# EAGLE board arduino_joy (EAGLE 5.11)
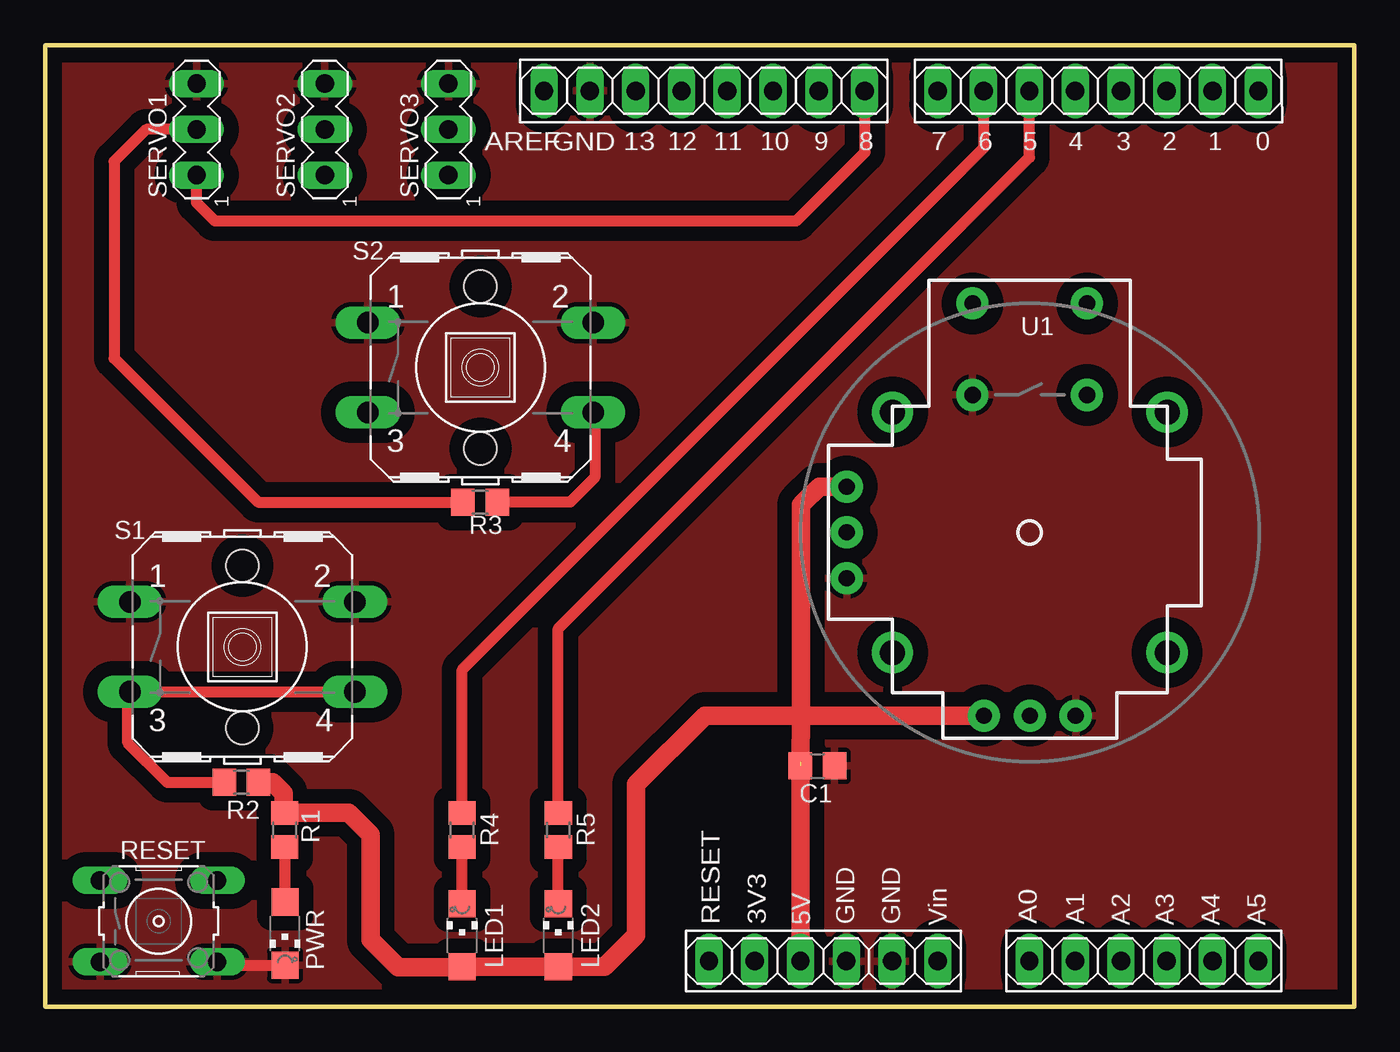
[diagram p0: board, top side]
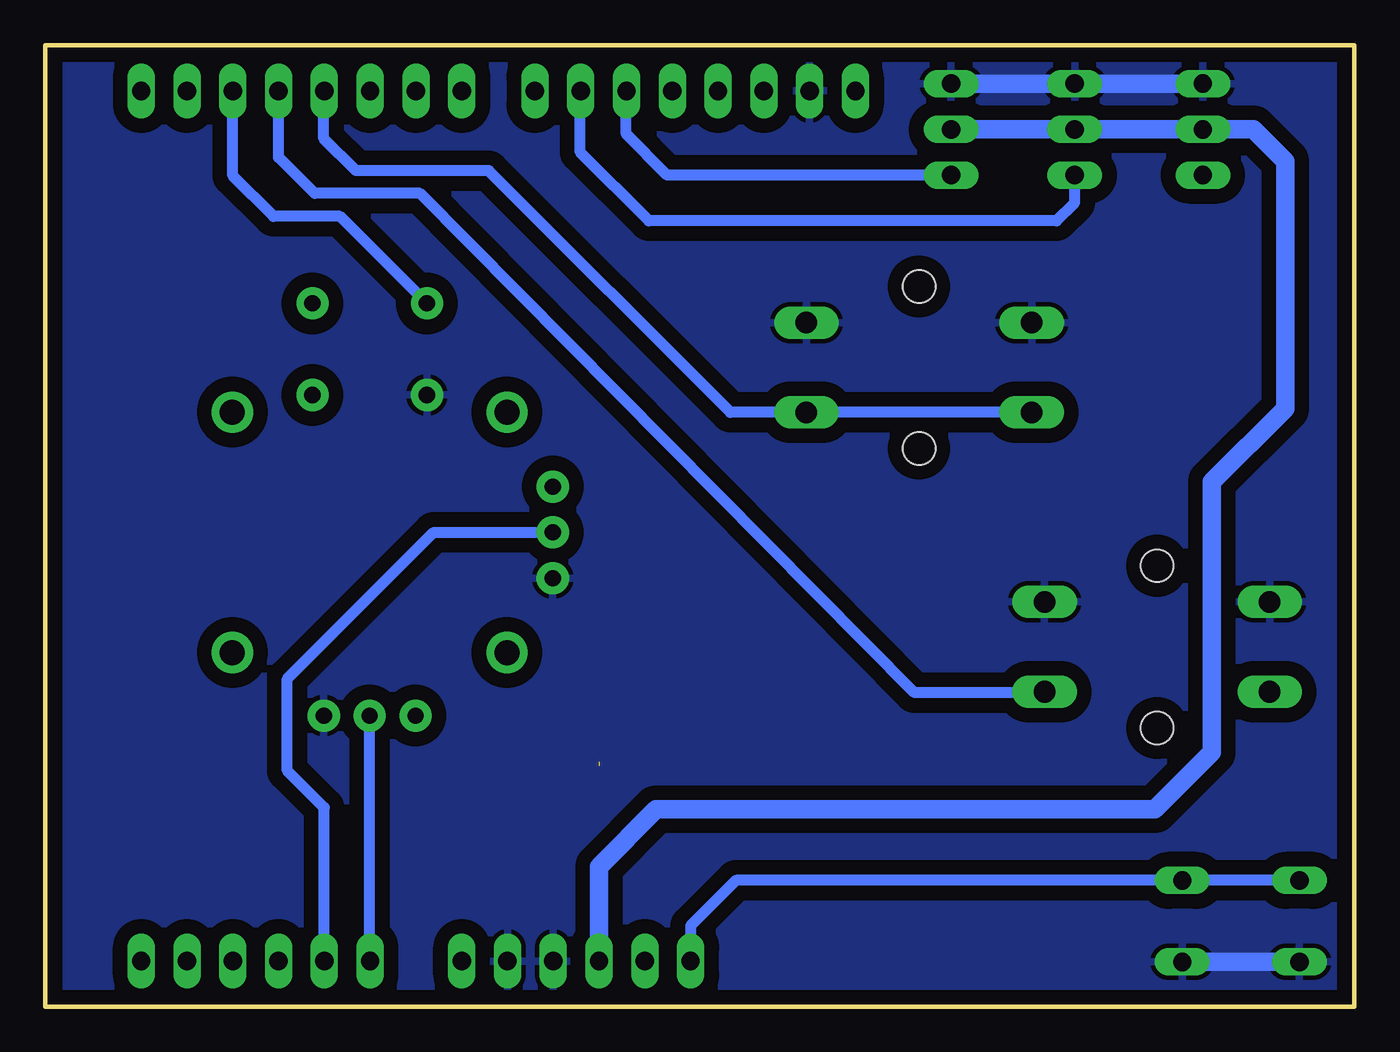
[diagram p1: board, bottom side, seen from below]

Size 72.64 x 53.34 mm. Coordinates in mm from the lower left corner, seen from the top.
Outline: 0,53.34 72.64,53.34 72.64,0 0,0 0,53.34
Copper layers (1*16): Top 0.035mm / dielectric 1.5mm / Bottom 0.035mm
Design rules "default *": minimum track width 16mil, minimum drill 24mil, track to track 8mil, track to pad 8mil, pad to pad 8mil, via to via 8mil, smd to smd 8mil, copper to edge 20mil, drill to drill 8mil, minimum pad ring 10mil, minimum via ring 8mil, stop-mask expansion 4mil, vias tented up to drill 0mil, thermal gap 10mil
Net classes: 0 default: width 0.254 mm, drill 0.305 mm, clearance 0.152 mm; 1 power: width 0.61 mm, drill 0.508 mm, clearance 0.152 mm; 2 gnd: width 0.305 mm, drill 0.508 mm, clearance 0.152 mm; 3 usbvcc: width 0.508 mm, drill 0.508 mm, clearance 0.152 mm; 4 aref: width 0.406 mm

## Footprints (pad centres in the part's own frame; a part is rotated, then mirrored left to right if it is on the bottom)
C0805 = smd 1.3 x 1.5: 1 -0.95,0; 2 0.95,0
1X08 = drill 1.016 long: 1 -8.89,0; 2 -6.35,0; 3 -3.81,0; 4 -1.27,0; 5 1.27,0; 6 3.81,0; 7 6.35,0; 8 8.89,0
1X06 = drill 1.016 long: 1 -6.35,0; 2 -3.81,0; 3 -1.27,0; 4 1.27,0; 5 3.81,0; 6 6.35,0
CHIPLED_1206 = smd 1.5 x 1.5: A 0,-1.75; C 0,1.75
R0805 = smd 1.3 x 1.5: 1 -0.95,0; 2 0.95,0
B3F-10XX = drill 1.016 long: 1 -3.251,2.261; 2 3.251,2.261; 3 -3.251,-2.261; 4 3.251,-2.261
B3F-40XX = drill 1.194 long: 1 -6.248,2.489; 2 6.248,2.489; 3 -6.248,-2.489; 4 6.248,-2.489 | hole 1.803: 0,-4.496; 0,4.496
MA03-1 = drill 1.016 long: 1 -2.54,0; 2 0,0; 3 2.54,0
JOYSTICK = drill 0.9 pad 1.778 round: B1A -3.175,12.7; B1B 3.175,12.7; B2A -3.175,7.62; B2B 3.175,7.62 | drill 0.889 pad 1.778 round: H1 -2.54,-10.16; H2 0,-10.16; H3 2.54,-10.16; V1 -10.16,2.54; V2 -10.16,0; V3 -10.16,-2.54 | drill 1.397 pad 2.286 round: MOUNT1 -7.62,6.668; MOUNT2 -7.62,-6.668; MOUNT3 7.62,-6.668; MOUNT4 7.62,6.668

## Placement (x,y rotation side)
C1  100nF  [C0805]  42.85,13.36 0 top
J1  [1X08]  58.42,50.8 180 top
J2  [1X06]  60.96,2.54 0 top
J3  [1X08]  36.58,50.8 180 top
LED1  [CHIPLED_1206]  23.14,3.96 0 top
LED2  [CHIPLED_1206]  28.47,3.96 0 top
POWER  [1X06]  43.18,2.54 0 top
PWR  [CHIPLED_1206]  13.31,4.06 180 top
R1  1k  [R0805]  13.28,9.8 90 top
R2  10k  [R0805]  10.9,12.45 180 top
R3  10k  [R0805]  24.13,27.99 0 top
R4  [R0805]  23.14,9.8 90 top
R5  [R0805]  28.47,9.8 90 top
RESET  [B3F-10XX]  6.3,4.75 0 top
S1  [B3F-40XX]  10.95,19.96 0 top
S2  [B3F-40XX]  24.16,35.46 0 top
SERVO1  [MA03-1]  8.41,48.67 90 top
SERVO2  [MA03-1]  15.52,48.67 90 top
SERVO3  [MA03-1]  22.38,48.67 90 top
U1  JOYSTICKPTH  [JOYSTICK]  54.64,26.31 0 top

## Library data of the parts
C1 R1-R5 = rcl
J1-J3 POWER = pinhead
LED1 LED2 PWR = led
RESET = switch-omron; MPN: B3F-1000; OC_FARNELL: 176432; OC_NEWARK: 36M3542
S1 S2 = switch-omron; MF: OMRON COMPONENTS USA; MPN: B3F-4000; OC_FARNELL: 176434; OC_NEWARK: 36K3105
SERVO1-SERVO3 = con-lstb; OC_FARNELL: unknown; OC_NEWARK: unknown
U1 = SparkFun

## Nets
+5V [usbvcc]: C1.1 LED1.A LED2.A POWER.3 R1.2 R2.1 R3.1 SERVO1.2 SERVO2.2 SERVO3.2 U1.H1 U1.V1
AREF: J3.8
GND [power]: C1.2 J3.7 POWER.4 POWER.5 PWR.C RESET.3 RESET.4 S1.1 S1.2 S2.1 S2.2 SERVO1.3 SERVO2.3 SERVO3.3 U1.B2A U1.H3 U1.V3
N$1: LED1.C R4.1
N$2: LED2.C R5.1
N$8: PWR.A R1.1
PB0: J3.1 SERVO1.1
PB1: J3.2 SERVO2.1
PB2: J3.3 SERVO3.1
PB3: J3.4
PB4: J3.5
PB5: J3.6
PC0: J2.1 U1.H2
PC1: J2.2 U1.V2
PC2: J2.3
PC3: J2.4
PC4: J2.5
PC5: J2.6
PD0: J1.1
PD1: J1.2
PD2: J1.3 U1.B1A
PD3: J1.4 R2.2 S1.3 S1.4
PD4: J1.5 R3.2 S2.3 S2.4
PD5: J1.6 R5.2
PD6: J1.7 R4.2
PD7: J1.8
RESET: POWER.1 RESET.1 RESET.2
VCC3O: POWER.2
VIN: POWER.6

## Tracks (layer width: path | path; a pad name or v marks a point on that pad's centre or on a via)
+5V  (1 unrouted)
  Top 0.61: 23.11,2.18 LED1.A | R3.1 11.81,27.99 3.84,35.97 3.84,46.89 5.61,48.67 SERVO1.2
  Top 1.016: POWER.3 41.91,13.59 41.94,16.15 | 41.94,16.15 U1.H1 | LED1.A LED2.A 31.04,2.21 32.79,3.96 32.79,12.34 36.6,16.15 41.94,16.15 | 23.11,2.18 19.58,2.18 18.06,3.71 18.06,9.55 16.86,10.75 R1.2 13.23,10.81 13.23,11.84 12.62,12.45 R2.1 | SERVO1.2 8.92,48.67 | U1.V1 42.95,28.85 41.94,27.84 41.94,16.15
  Bottom 1.016: SERVO3.2 SERVO2.2 SERVO1.2 5.61,48.67 3.84,46.89 3.84,33.17 7.9,29.11 7.9,14.12 11.07,10.95 38.74,10.95 41.91,7.77 POWER.3
GND
  Top 0.61: PWR.C 9.73,2.31 RESET.4
  Bottom 1.016: SERVO1.3 SERVO2.3 SERVO3.3 | RESET.3 RESET.4
  pour Top (isolate 0.813): -0.74,53.75 73.18,53.75 73.18,-0.36 -0.48,-0.36
  pour Bottom (isolate 0.813): -0.99,54 73.18,53.75 73.18,-0.36 -0.23,-0.36
N$1
  Top 0.61: LED1.C R4.1
N$2
  Top 0.61: LED2.C R5.1
N$8
  Top 0.61: PWR.A 13.31,8.83 R1.1
PB0
  Top 0.61: SERVO1.1 8.41,44.6 9.42,43.59 41.68,43.59 45.49,47.4 45.49,50.77 J3.1
PB1
  Bottom 0.61: SERVO2.1 15.52,44.6 16.54,43.59 39.14,43.59 42.95,47.4 42.95,50.77 J3.2
PB2
  Bottom 0.61: SERVO3.1 38.13,46.13 40.41,48.41 40.41,50.77 J3.3
PC0
  Bottom 0.406: J2.1 54.64,2.57
  Bottom 0.61: 54.64,2.57 U1.H2
PC1
  Bottom 0.61: J2.2 57.15,11.05 59.21,13.11 59.21,18.19 51.08,26.31 U1.V2
PD2
  Bottom 0.61: J1.3 62.23,46.1 59.97,43.84 56.29,43.84 U1.B1A
PD3
  Top 0.61: S1.4 S1.3 4.6,17.37 4.6,14.63 6.78,12.45 R2.2
  Bottom 0.61: J1.4 59.69,47.12 57.68,45.11 51.84,45.11 24.41,17.42 17.25,17.42 S1.4
PD4
  Top 0.61: R3.2 29.13,27.99 30.51,29.36 30.51,32.87 S2.4
  Bottom 0.61: J1.5 57.18,50.77 57.18,48.16 55.4,46.38 48.03,46.38 34.62,32.97 S2.4 S2.3
PD5
  Top 0.61: J1.6 54.61,47.12 28.47,20.98 R5.2
PD6
  Top 0.61: R4.2 23.14,18.69 52.1,47.65 52.1,50.77 J1.7
RESET
  Bottom 0.61: POWER.1 36.83,4.5 34.32,7.01 RESET.2 RESET.1

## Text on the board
tNames: AREF | GND | 13 | 12 | 11 | 10 | 9 | 8 | 7 | 6 | 5 | 4 | 3 | 2 | 1 | 0 | 1 | 1 | 1 | RESET | 3V3 | 5V | GND | GND | Vin | A0 | A1 | A2 | A3 | A4 | A5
